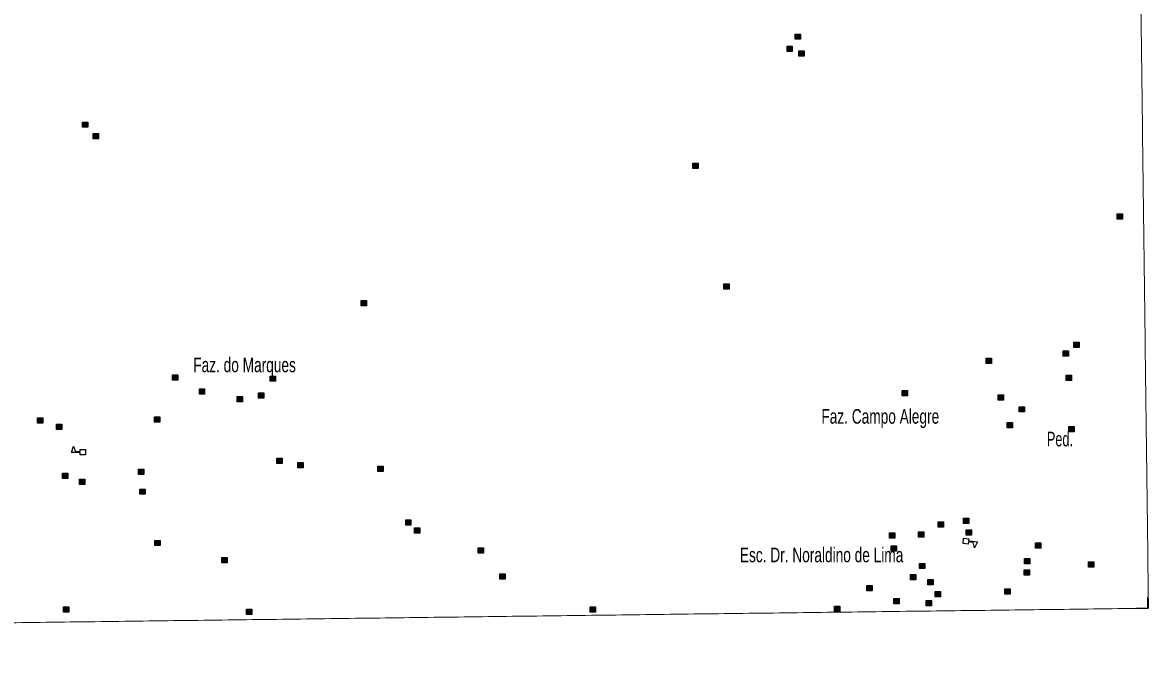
# Model space of a CAD drawing. Extents: x 265.7 to 292.1, y 7676.2 to 7704.2.
# Drawn here: x 285.94 to 292.1, y 7676.18 to 7679.73 of the extents above; entities that cross this region are included whole.
import ezdxf

# ---------------------------------------------------------------- set-up
doc = ezdxf.new("R2010")
doc.units = 0
doc.header["$LTSCALE"] = 0.032
for name, color, linetype, lineweight in [('2', 7, 'Continuous', 25), ('4', 7, 'Continuous', 25), ('63', 7, 'Continuous', 13)]:
    doc.layers.add(name, color=color, linetype=linetype, lineweight=lineweight)
doc.layers.add('61', color=7, linetype='Continuous')

msp = doc.modelspace()

# ---------------------------------------------------------------- hatches: boundary and pattern name
at = {"layer": '2'}
for points in [[(290.1676, 7679.6641), (290.1966, 7679.6641), (290.1966, 7679.6351), (290.1676, 7679.6351)], [(290.1231, 7679.5982), (290.1521, 7679.5982), (290.1521, 7679.5692), (290.1231, 7679.5692)], [(290.1877, 7679.5723), (290.2167, 7679.5723), (290.2167, 7679.5433), (290.1877, 7679.5433)], [(286.2663, 7679.1826), (286.2953, 7679.1826), (286.2953, 7679.1536), (286.2663, 7679.1536)], [(286.3237, 7679.1198), (286.3527, 7679.1198), (286.3527, 7679.0908), (286.3237, 7679.0908)], [(289.6083, 7678.9566), (289.6373, 7678.9566), (289.6373, 7678.9276), (289.6083, 7678.9276)], [(291.9301, 7678.6798), (291.9591, 7678.6798), (291.9591, 7678.6508), (291.9301, 7678.6508)], [(289.777, 7678.2965), (289.806, 7678.2965), (289.806, 7678.2675), (289.777, 7678.2675)], [(287.7909, 7678.2053), (287.8199, 7678.2053), (287.8199, 7678.1763), (287.7909, 7678.1763)], [(291.6928, 7677.9785), (291.7218, 7677.9785), (291.7218, 7677.9495), (291.6928, 7677.9495)], [(291.2128, 7677.8897), (291.2418, 7677.8897), (291.2418, 7677.8607), (291.2128, 7677.8607)], [(291.6347, 7677.9302), (291.6637, 7677.9302), (291.6637, 7677.9012), (291.6347, 7677.9012)], [(286.7577, 7677.7994), (286.7867, 7677.7994), (286.7867, 7677.7704), (286.7577, 7677.7704)], [(287.2936, 7677.7929), (287.3226, 7677.7929), (287.3226, 7677.7639), (287.2936, 7677.7639)], [(291.6517, 7677.797), (291.6807, 7677.797), (291.6807, 7677.768), (291.6517, 7677.768)], [(286.9055, 7677.7219), (286.9345, 7677.7219), (286.9345, 7677.6929), (286.9055, 7677.6929)], [(287.2291, 7677.701), (287.2581, 7677.701), (287.2581, 7677.672), (287.2291, 7677.672)], [(290.7542, 7677.7139), (290.7832, 7677.7139), (290.7832, 7677.6849), (290.7542, 7677.6849)], [(291.2789, 7677.6905), (291.3079, 7677.6905), (291.3079, 7677.6615), (291.2789, 7677.6615)], [(287.1129, 7677.6799), (287.1419, 7677.6799), (287.1419, 7677.6509), (287.1129, 7677.6509)], [(286.6593, 7677.5694), (286.6883, 7677.5694), (286.6883, 7677.5404), (286.6593, 7677.5404)], [(291.395, 7677.625), (291.424, 7677.625), (291.424, 7677.596), (291.395, 7677.596)], [(286.0201, 7677.5644), (286.0491, 7677.5644), (286.0491, 7677.5354), (286.0201, 7677.5354)], [(286.1234, 7677.5298), (286.1524, 7677.5298), (286.1524, 7677.5008), (286.1234, 7677.5008)], [(291.3281, 7677.5379), (291.3571, 7677.5379), (291.3571, 7677.5089), (291.3281, 7677.5089)], [(291.6655, 7677.5169), (291.6945, 7677.5169), (291.6945, 7677.4879), (291.6655, 7677.4879)], [(287.3292, 7677.3433), (287.3582, 7677.3433), (287.3582, 7677.3143), (287.3292, 7677.3143)], [(287.4446, 7677.32), (287.4736, 7677.32), (287.4736, 7677.291), (287.4446, 7677.291)], [(286.1557, 7677.261), (286.1847, 7677.261), (286.1847, 7677.232), (286.1557, 7677.232)], [(286.5729, 7677.2828), (286.6019, 7677.2828), (286.6019, 7677.2538), (286.5729, 7677.2538)], [(287.8828, 7677.2998), (287.9118, 7677.2998), (287.9118, 7677.2708), (287.8828, 7677.2708)], [(286.2492, 7677.228), (286.2782, 7677.228), (286.2782, 7677.199), (286.2492, 7677.199)], [(286.5802, 7677.1747), (286.6092, 7677.1747), (286.6092, 7677.1457), (286.5802, 7677.1457)], [(291.09, 7677.0149), (291.119, 7677.0149), (291.119, 7676.9859), (291.09, 7676.9859)], [(288.0352, 7677.0059), (288.0642, 7677.0059), (288.0642, 7676.9769), (288.0352, 7676.9769)], [(288.0838, 7676.9625), (288.1128, 7676.9625), (288.1128, 7676.9335), (288.0838, 7676.9335)], [(290.9503, 7676.9947), (290.9793, 7676.9947), (290.9793, 7676.9657), (290.9503, 7676.9657)], [(291.1038, 7676.9519), (291.1328, 7676.9519), (291.1328, 7676.9229), (291.1038, 7676.9229)], [(286.6624, 7676.8938), (286.6914, 7676.8938), (286.6914, 7676.8648), (286.6624, 7676.8648)], [(290.6849, 7676.9342), (290.7139, 7676.9342), (290.7139, 7676.9052), (290.6849, 7676.9052)], [(290.843, 7676.9398), (290.872, 7676.9398), (290.872, 7676.9108), (290.843, 7676.9108)], [(288.4315, 7676.8526), (288.4605, 7676.8526), (288.4605, 7676.8236), (288.4315, 7676.8236)], [(290.693, 7676.8632), (290.722, 7676.8632), (290.722, 7676.8342), (290.693, 7676.8342)], [(291.4839, 7676.8809), (291.5129, 7676.8809), (291.5129, 7676.8519), (291.4839, 7676.8519)], [(287.0289, 7676.8002), (287.0579, 7676.8002), (287.0579, 7676.7712), (287.0289, 7676.7712)], [(290.8487, 7676.768), (290.8777, 7676.768), (290.8777, 7676.739), (290.8487, 7676.739)], [(291.424, 7676.7938), (291.453, 7676.7938), (291.453, 7676.7648), (291.424, 7676.7648)], [(291.7736, 7676.7761), (291.8026, 7676.7761), (291.8026, 7676.7471), (291.7736, 7676.7471)], [(288.551, 7676.7099), (288.58, 7676.7099), (288.58, 7676.6809), (288.551, 7676.6809)], [(290.7995, 7676.7073), (290.8285, 7676.7073), (290.8285, 7676.6783), (290.7995, 7676.6783)], [(291.4217, 7676.7324), (291.4507, 7676.7324), (291.4507, 7676.7034), (291.4217, 7676.7034)], [(290.5598, 7676.6469), (290.5888, 7676.6469), (290.5888, 7676.6179), (290.5598, 7676.6179)], [(290.8947, 7676.6792), (290.9237, 7676.6792), (290.9237, 7676.6502), (290.8947, 7676.6502)], [(290.935, 7676.613), (290.964, 7676.613), (290.964, 7676.584), (290.935, 7676.584)], [(291.3152, 7676.6292), (291.3442, 7676.6292), (291.3442, 7676.6002), (291.3152, 7676.6002)], [(286.1613, 7676.5299), (286.1903, 7676.5299), (286.1903, 7676.5009), (286.1613, 7676.5009)], [(287.1629, 7676.5177), (287.1919, 7676.5177), (287.1919, 7676.4887), (287.1629, 7676.4887)], [(289.0457, 7676.5307), (289.0747, 7676.5307), (289.0747, 7676.5017), (289.0457, 7676.5017)], [(290.3838, 7676.534), (290.4128, 7676.534), (290.4128, 7676.505), (290.3838, 7676.505)], [(290.7083, 7676.575), (290.7373, 7676.575), (290.7373, 7676.546), (290.7083, 7676.546)], [(290.885, 7676.5653), (290.914, 7676.5653), (290.914, 7676.5363), (290.885, 7676.5363)]]:
    msp.add_hatch(color=256, dxfattribs=at).paths.add_polyline_path(points)

# ---------------------------------------------------------------- linework, layer by layer
for points in [[(290.1676, 7679.6641), (290.1966, 7679.6641), (290.1966, 7679.6351), (290.1676, 7679.6351)], [(290.1231, 7679.5982), (290.1521, 7679.5982), (290.1521, 7679.5692), (290.1231, 7679.5692)], [(290.1877, 7679.5723), (290.2167, 7679.5723), (290.2167, 7679.5433), (290.1877, 7679.5433)], [(286.2663, 7679.1826), (286.2953, 7679.1826), (286.2953, 7679.1536), (286.2663, 7679.1536)], [(286.3237, 7679.1198), (286.3527, 7679.1198), (286.3527, 7679.0908), (286.3237, 7679.0908)], [(289.6083, 7678.9566), (289.6373, 7678.9566), (289.6373, 7678.9276), (289.6083, 7678.9276)], [(291.9301, 7678.6798), (291.9591, 7678.6798), (291.9591, 7678.6508), (291.9301, 7678.6508)], [(289.777, 7678.2965), (289.806, 7678.2965), (289.806, 7678.2675), (289.777, 7678.2675)], [(287.7909, 7678.2053), (287.8199, 7678.2053), (287.8199, 7678.1763), (287.7909, 7678.1763)], [(291.6928, 7677.9785), (291.7218, 7677.9785), (291.7218, 7677.9495), (291.6928, 7677.9495)], [(291.2128, 7677.8897), (291.2418, 7677.8897), (291.2418, 7677.8607), (291.2128, 7677.8607)], [(291.6347, 7677.9302), (291.6637, 7677.9302), (291.6637, 7677.9012), (291.6347, 7677.9012)], [(286.7577, 7677.7994), (286.7867, 7677.7994), (286.7867, 7677.7704), (286.7577, 7677.7704)], [(287.2936, 7677.7929), (287.3226, 7677.7929), (287.3226, 7677.7639), (287.2936, 7677.7639)], [(291.6517, 7677.797), (291.6807, 7677.797), (291.6807, 7677.768), (291.6517, 7677.768)], [(286.9055, 7677.7219), (286.9345, 7677.7219), (286.9345, 7677.6929), (286.9055, 7677.6929)], [(287.2291, 7677.701), (287.2581, 7677.701), (287.2581, 7677.672), (287.2291, 7677.672)], [(290.7542, 7677.7139), (290.7832, 7677.7139), (290.7832, 7677.6849), (290.7542, 7677.6849)], [(291.2789, 7677.6905), (291.3079, 7677.6905), (291.3079, 7677.6615), (291.2789, 7677.6615)], [(287.1129, 7677.6799), (287.1419, 7677.6799), (287.1419, 7677.6509), (287.1129, 7677.6509)], [(286.6593, 7677.5694), (286.6883, 7677.5694), (286.6883, 7677.5404), (286.6593, 7677.5404)], [(291.395, 7677.625), (291.424, 7677.625), (291.424, 7677.596), (291.395, 7677.596)], [(286.0201, 7677.5644), (286.0491, 7677.5644), (286.0491, 7677.5354), (286.0201, 7677.5354)], [(286.1234, 7677.5298), (286.1524, 7677.5298), (286.1524, 7677.5008), (286.1234, 7677.5008)], [(291.3281, 7677.5379), (291.3571, 7677.5379), (291.3571, 7677.5089), (291.3281, 7677.5089)], [(291.6655, 7677.5169), (291.6945, 7677.5169), (291.6945, 7677.4879), (291.6655, 7677.4879)], [(287.3292, 7677.3433), (287.3582, 7677.3433), (287.3582, 7677.3143), (287.3292, 7677.3143)], [(287.4446, 7677.32), (287.4736, 7677.32), (287.4736, 7677.291), (287.4446, 7677.291)], [(286.1557, 7677.261), (286.1847, 7677.261), (286.1847, 7677.232), (286.1557, 7677.232)], [(286.5729, 7677.2828), (286.6019, 7677.2828), (286.6019, 7677.2538), (286.5729, 7677.2538)], [(287.8828, 7677.2998), (287.9118, 7677.2998), (287.9118, 7677.2708), (287.8828, 7677.2708)], [(286.2492, 7677.228), (286.2782, 7677.228), (286.2782, 7677.199), (286.2492, 7677.199)], [(286.5802, 7677.1747), (286.6092, 7677.1747), (286.6092, 7677.1457), (286.5802, 7677.1457)], [(291.09, 7677.0149), (291.119, 7677.0149), (291.119, 7676.9859), (291.09, 7676.9859)], [(288.0352, 7677.0059), (288.0642, 7677.0059), (288.0642, 7676.9769), (288.0352, 7676.9769)], [(288.0838, 7676.9625), (288.1128, 7676.9625), (288.1128, 7676.9335), (288.0838, 7676.9335)], [(290.9503, 7676.9947), (290.9793, 7676.9947), (290.9793, 7676.9657), (290.9503, 7676.9657)], [(291.1038, 7676.9519), (291.1328, 7676.9519), (291.1328, 7676.9229), (291.1038, 7676.9229)], [(286.6624, 7676.8938), (286.6914, 7676.8938), (286.6914, 7676.8648), (286.6624, 7676.8648)], [(290.6849, 7676.9342), (290.7139, 7676.9342), (290.7139, 7676.9052), (290.6849, 7676.9052)], [(290.843, 7676.9398), (290.872, 7676.9398), (290.872, 7676.9108), (290.843, 7676.9108)], [(288.4315, 7676.8526), (288.4605, 7676.8526), (288.4605, 7676.8236), (288.4315, 7676.8236)], [(290.693, 7676.8632), (290.722, 7676.8632), (290.722, 7676.8342), (290.693, 7676.8342)], [(291.4839, 7676.8809), (291.5129, 7676.8809), (291.5129, 7676.8519), (291.4839, 7676.8519)], [(287.0289, 7676.8002), (287.0579, 7676.8002), (287.0579, 7676.7712), (287.0289, 7676.7712)], [(290.8487, 7676.768), (290.8777, 7676.768), (290.8777, 7676.739), (290.8487, 7676.739)], [(291.424, 7676.7938), (291.453, 7676.7938), (291.453, 7676.7648), (291.424, 7676.7648)], [(291.7736, 7676.7761), (291.8026, 7676.7761), (291.8026, 7676.7471), (291.7736, 7676.7471)], [(288.551, 7676.7099), (288.58, 7676.7099), (288.58, 7676.6809), (288.551, 7676.6809)], [(290.7995, 7676.7073), (290.8285, 7676.7073), (290.8285, 7676.6783), (290.7995, 7676.6783)], [(291.4217, 7676.7324), (291.4507, 7676.7324), (291.4507, 7676.7034), (291.4217, 7676.7034)], [(290.5598, 7676.6469), (290.5888, 7676.6469), (290.5888, 7676.6179), (290.5598, 7676.6179)], [(290.8947, 7676.6792), (290.9237, 7676.6792), (290.9237, 7676.6502), (290.8947, 7676.6502)], [(290.935, 7676.613), (290.964, 7676.613), (290.964, 7676.584), (290.935, 7676.584)], [(291.3152, 7676.6292), (291.3442, 7676.6292), (291.3442, 7676.6002), (291.3152, 7676.6002)], [(286.1613, 7676.5299), (286.1903, 7676.5299), (286.1903, 7676.5009), (286.1613, 7676.5009)], [(287.1629, 7676.5177), (287.1919, 7676.5177), (287.1919, 7676.4887), (287.1629, 7676.4887)], [(289.0457, 7676.5307), (289.0747, 7676.5307), (289.0747, 7676.5017), (289.0457, 7676.5017)], [(290.3838, 7676.534), (290.4128, 7676.534), (290.4128, 7676.505), (290.3838, 7676.505)], [(290.7083, 7676.575), (290.7373, 7676.575), (290.7373, 7676.546), (290.7083, 7676.546)], [(290.885, 7676.5653), (290.914, 7676.5653), (290.914, 7676.5363), (290.885, 7676.5363)]]:
    msp.add_lwpolyline(points, close=True, dxfattribs=at)
at = {"layer": '4'}
for points in [[(286.2529, 7677.3743), (286.2045, 7677.3743), (286.2161, 7677.4082), (286.2268, 7677.3792), (286.2529, 7677.3792)], [(286.2529, 7677.3792), (286.2529, 7677.3913), (286.2819, 7677.3913), (286.2819, 7677.3623), (286.2529, 7677.3623), (286.2529, 7677.3743)], [(291.1168, 7676.8857), (291.1155, 7676.8736), (291.0867, 7676.8767), (291.0897, 7676.9055), (291.1185, 7676.9025), (291.1173, 7676.8905)], [(291.1173, 7676.8905), (291.1654, 7676.8855), (291.1503, 7676.853), (291.1427, 7676.8829), (291.1168, 7676.8857)]]:
    msp.add_lwpolyline(points, dxfattribs=at)
at = {"layer": '63', "lineweight": 25}
msp.add_lwpolyline([(292.0373, 7676.5221), (292.0989, 7676.5221), (292.0989, 7676.5828)], dxfattribs=at)
at = {"layer": '63'}
for points in [[(292.1022, 7676.5221), (292.0951, 7677.087), (292.088, 7677.6519), (292.081, 7678.2168), (292.0739, 7678.7818), (292.0668, 7679.3467), (292.0598, 7679.9116), (292.0527, 7680.4765), (292.0457, 7681.0414), (292.0386, 7681.6064), (292.0316, 7682.1713), (292.0245, 7682.7362), (292.0175, 7683.3011), (292.0104, 7683.866), (292.0034, 7684.431), (291.9963, 7684.9959), (291.9893, 7685.5608), (291.9822, 7686.1257), (291.9752, 7686.6906), (291.9681, 7687.2556), (291.9611, 7687.8205), (291.9541, 7688.3854), (291.947, 7688.9503), (291.94, 7689.5152), (291.933, 7690.0801), (291.9259, 7690.6451), (291.9189, 7691.21), (291.9119, 7691.7749), (291.9049, 7692.3398), (291.8978, 7692.9047), (291.8908, 7693.4696), (291.8838, 7694.0345), (291.8768, 7694.5995), (291.8698, 7695.1644), (291.8628, 7695.7293), (291.8557, 7696.2942), (291.8487, 7696.8591), (291.8417, 7697.424), (291.8347, 7697.9889), (291.8277, 7698.5539), (291.8207, 7699.1188), (291.8137, 7699.6837), (291.8067, 7700.2486), (291.7997, 7700.8135), (291.7927, 7701.3784), (291.7857, 7701.9433), (291.7787, 7702.5082), (291.7717, 7703.0731), (291.7647, 7703.638), (291.7577, 7704.203)], [(266.1055, 7676.1764), (266.6361, 7676.1838), (267.1667, 7676.1913), (267.6972, 7676.1987), (268.2278, 7676.2061), (268.7584, 7676.2135), (269.2889, 7676.2209), (269.8195, 7676.2283), (270.3501, 7676.2356), (270.8806, 7676.2429), (271.4112, 7676.2502), (271.9418, 7676.2575), (272.4723, 7676.2648), (273.0029, 7676.2721), (273.5335, 7676.2793), (274.064, 7676.2865), (274.5946, 7676.2937), (275.1251, 7676.3009), (275.6557, 7676.3081), (276.1862, 7676.3153), (276.7168, 7676.3224), (277.2473, 7676.3295), (277.7779, 7676.3366), (278.3084, 7676.3437), (278.839, 7676.3508), (279.3695, 7676.3578), (279.9, 7676.3649), (280.4306, 7676.3719), (280.9611, 7676.3789), (281.4917, 7676.3859), (282.0222, 7676.3929), (282.5527, 7676.3998), (283.0833, 7676.4067), (283.6138, 7676.4137), (284.1443, 7676.4206), (284.6749, 7676.4275), (285.2054, 7676.4343), (285.7359, 7676.4412), (286.2665, 7676.448), (286.797, 7676.4548), (287.3275, 7676.4616), (287.858, 7676.4684), (288.3886, 7676.4752), (288.9191, 7676.4819), (289.4496, 7676.4887), (289.9801, 7676.4954), (290.5106, 7676.5021), (291.0411, 7676.5087), (291.5717, 7676.5154), (292.1022, 7676.5221)]]:
    msp.add_spline(points, degree=3, dxfattribs=at)

# ---------------------------------------------------------------- texts
at = {"layer": '61'}
for s, width, p in [('Faz. do Marques', 0.7, (286.872, 7677.8137)), ('Faz. Campo Alegre', 0.7, (290.3113, 7677.532)), ('Ped.', 0.65, (291.5459, 7677.408)), ('Esc. Dr. Noraldino de Lima', 0.7, (289.8651, 7676.7741))]:
    msp.add_text(s, height=0.08, dxfattribs=dict(at, width=width)).set_placement(p)

doc.saveas('drawing.dxf')
